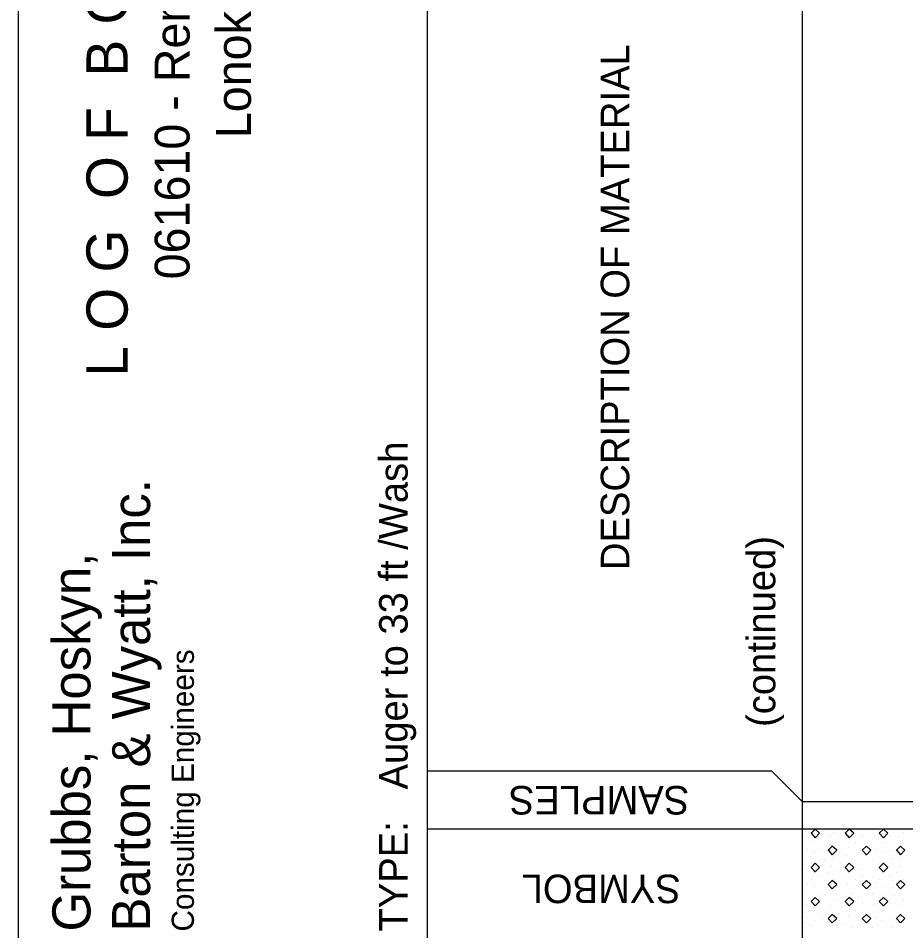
# Model space of a CAD drawing. Extents: x 1313964 to 1316843, y 2087046 to 2096619.
# Drawn here: x 1314075.31 to 1314091.13, y 2089930.61 to 2089946.89 of the extents above; entities that cross this region are included whole.
import ezdxf

# ---------------------------------------------------------------- set-up
doc = ezdxf.new("R2010")
doc.units = 0
doc.layers.add('B-Sub-Contour', color=7, linetype='Continuous')
doc.layers.add('Default', color=7, linetype='Continuous')

# ---------------------------------------------------------------- blocks, each defined once
blk = doc.blocks.new('POINT_DISPLAY')
at = {"layer": 'Default'}
blk.add_line((0, 0), (0, 0), dxfattribs=at)

msp = doc.modelspace()

# ---------------------------------------------------------------- linework, layer by layer
at = {"layer": 'B-Sub-Contour'}
for points in [[(1314136.725, 2089928.164), (1314136.725, 2089971.035), (1314075.306, 2089971.035), (1314075.306, 2089928.164), (1314136.725, 2089928.164)], [(1314082.603, 2089928.164), (1314082.603, 2089971.035)], [(1314089.292, 2089928.164), (1314089.292, 2089971.035)], [(1314088.745, 2089933.454), (1314082.603, 2089933.454)], [(1314089.292, 2089932.907), (1314088.745, 2089933.454)], [(1314134.292, 2089932.907), (1314089.292, 2089932.907)], [(1314134.292, 2089932.421), (1314082.603, 2089932.421)]]:
    msp.add_lwpolyline(points, dxfattribs=at)
for points in [[(1314089.517, 2089932.421), (1314089.444, 2089932.348), (1314089.517, 2089932.269), (1314089.597, 2089932.348)], [(1314090.126, 2089932.421), (1314090.053, 2089932.348), (1314090.126, 2089932.269), (1314090.205, 2089932.348)], [(1314090.734, 2089932.421), (1314090.661, 2089932.348), (1314090.734, 2089932.269), (1314090.813, 2089932.348)], [(1314089.822, 2089932.117), (1314089.749, 2089932.044), (1314089.822, 2089931.965), (1314089.901, 2089932.044)], [(1314090.43, 2089932.117), (1314090.357, 2089932.044), (1314090.43, 2089931.965), (1314090.509, 2089932.044)], [(1314091.038, 2089932.117), (1314090.965, 2089932.044), (1314091.038, 2089931.965), (1314091.117, 2089932.044)], [(1314089.517, 2089931.813), (1314089.444, 2089931.74), (1314089.517, 2089931.661), (1314089.597, 2089931.74)], [(1314090.126, 2089931.813), (1314090.053, 2089931.74), (1314090.126, 2089931.661), (1314090.205, 2089931.74)], [(1314090.734, 2089931.813), (1314090.661, 2089931.74), (1314090.734, 2089931.661), (1314090.813, 2089931.74)], [(1314089.822, 2089931.508), (1314089.749, 2089931.436), (1314089.822, 2089931.356), (1314089.901, 2089931.436)], [(1314090.43, 2089931.508), (1314090.357, 2089931.436), (1314090.43, 2089931.356), (1314090.509, 2089931.436)], [(1314091.038, 2089931.508), (1314090.965, 2089931.436), (1314091.038, 2089931.356), (1314091.117, 2089931.436)], [(1314089.517, 2089931.204), (1314089.444, 2089931.131), (1314089.517, 2089931.052), (1314089.597, 2089931.131)], [(1314090.126, 2089931.204), (1314090.053, 2089931.131), (1314090.126, 2089931.052), (1314090.205, 2089931.131)], [(1314090.734, 2089931.204), (1314090.661, 2089931.131), (1314090.734, 2089931.052), (1314090.813, 2089931.131)], [(1314089.822, 2089930.9), (1314089.749, 2089930.827), (1314089.822, 2089930.748), (1314089.901, 2089930.827)], [(1314090.43, 2089930.9), (1314090.357, 2089930.827), (1314090.43, 2089930.748), (1314090.509, 2089930.827)], [(1314091.038, 2089930.9), (1314090.965, 2089930.827), (1314091.038, 2089930.748), (1314091.117, 2089930.827)]]:
    msp.add_lwpolyline(points, close=True, dxfattribs=at)

# ---------------------------------------------------------------- block references
at = {"layer": 'B-Sub-Contour', "xscale": 0.019951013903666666, "yscale": 0.019951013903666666, "rotation": 90}
for p in [(1314089.353, 2089932.285), (1314089.444, 2089932.37), (1314089.627, 2089932.31), (1314089.782, 2089932.282), (1314089.87, 2089932.37), (1314089.992, 2089932.249), (1314090.113, 2089932.31), (1314090.357, 2089932.31), (1314090.569, 2089932.285), (1314090.661, 2089932.37), (1314090.843, 2089932.31), (1314090.998, 2089932.282), (1314091.086, 2089932.37), (1314089.384, 2089932.066), (1314089.505, 2089932.188), (1314089.749, 2089932.066), (1314089.931, 2089932.127), (1314090.113, 2089932.089), (1314090.235, 2089932.188), (1314090.478, 2089932.127), (1314090.6, 2089932.066), (1314090.722, 2089932.188), (1314090.965, 2089932.066), (1314089.439, 2089931.926), (1314089.505, 2089932.006), (1314089.643, 2089932.036), (1314089.829, 2089931.918), (1314089.956, 2089932.011), (1314090.053, 2089931.945), (1314090.296, 2089932.006), (1314090.417, 2089931.945), (1314090.655, 2089931.926), (1314090.722, 2089932.006), (1314090.86, 2089932.036), (1314091.045, 2089931.918), (1314089.323, 2089931.884), (1314089.566, 2089931.762), (1314089.688, 2089931.884), (1314089.809, 2089931.762), (1314089.992, 2089931.823), (1314090.174, 2089931.884), (1314090.539, 2089931.884), (1314090.782, 2089931.762), (1314090.904, 2089931.884), (1314091.026, 2089931.762), (1314089.323, 2089931.58), (1314089.384, 2089931.702), (1314089.505, 2089931.641), (1314089.627, 2089931.58), (1314089.749, 2089931.641), (1314089.931, 2089931.702), (1314090.113, 2089931.641), (1314090.296, 2089931.702), (1314090.357, 2089931.58), (1314090.539, 2089931.58), (1314090.6, 2089931.702), (1314090.722, 2089931.641), (1314090.843, 2089931.58), (1314090.965, 2089931.641), (1314089.384, 2089931.458), (1314089.444, 2089931.519), (1314089.688, 2089931.498), (1314089.809, 2089931.458), (1314089.87, 2089931.519), (1314090.1, 2089931.441), (1314090.235, 2089931.519), (1314090.417, 2089931.505), (1314090.6, 2089931.458), (1314090.661, 2089931.519), (1314090.904, 2089931.498), (1314091.026, 2089931.458), (1314091.086, 2089931.519), (1314089.323, 2089931.276), (1314089.505, 2089931.398), (1314089.566, 2089931.276), (1314089.704, 2089931.378), (1314089.809, 2089931.276), (1314089.931, 2089931.398), (1314090.174, 2089931.276), (1314090.296, 2089931.398), (1314090.478, 2089931.337), (1314090.539, 2089931.276), (1314090.722, 2089931.398), (1314090.782, 2089931.276), (1314090.921, 2089931.378), (1314091.026, 2089931.276), (1314089.444, 2089931.154), (1314089.627, 2089931.093), (1314089.696, 2089931.231), (1314089.87, 2089931.154), (1314090.053, 2089931.215), (1314090.113, 2089931.093), (1314090.296, 2089931.218), (1314090.357, 2089931.093), (1314090.661, 2089931.154), (1314090.843, 2089931.093), (1314090.912, 2089931.231), (1314091.086, 2089931.154), (1314089.353, 2089931.069), (1314089.505, 2089930.972), (1314089.782, 2089931.066), (1314089.992, 2089931.033), (1314090.235, 2089930.972), (1314090.569, 2089931.069), (1314090.722, 2089930.972), (1314090.998, 2089931.066), (1314089.384, 2089930.85), (1314089.505, 2089930.789), (1314089.643, 2089930.82), (1314089.749, 2089930.85), (1314089.931, 2089930.911), (1314089.956, 2089930.795), (1314090.113, 2089930.873), (1314090.296, 2089930.789), (1314090.478, 2089930.911), (1314090.6, 2089930.85), (1314090.722, 2089930.789), (1314090.86, 2089930.82), (1314090.965, 2089930.85), (1314089.323, 2089930.668), (1314089.439, 2089930.71), (1314089.688, 2089930.668), (1314089.829, 2089930.701), (1314090.053, 2089930.729), (1314090.174, 2089930.668), (1314090.417, 2089930.729), (1314090.539, 2089930.668), (1314090.655, 2089930.71), (1314090.904, 2089930.668), (1314091.045, 2089930.701)]:
    msp.add_blockref('POINT_DISPLAY', p, dxfattribs=at)

# ---------------------------------------------------------------- texts
at = {"layer": 'B-Sub-Contour'}
for s, height, rotation, p in [('L O G  O F  B O R I N G  N O.  S2', 0.7352, 90, (1314077.257, 2089940.493)), ('061610 - Remington Road over I-40', 0.62209, 90, (1314078.361, 2089942.229)), ('Lonoke County, Arkansas', 0.62209, 90, (1314079.455, 2089944.747)), ('DESCRIPTION OF MATERIAL', 0.50899, 90, (1314086.202, 2089937.043)), ('TYPE:   Auger to 33 ft /Wash', 0.50899, 90, (1314082.25, 2089930.596)), ('Barton & Wyatt, Inc.', 0.67865, 90, (1314077.657, 2089930.596)), ('(continued)', 0.50899, 90, (1314088.806, 2089934.245)), ('Grubbs, Hoskyn,', 0.67865, 90, (1314076.593, 2089930.596)), ('Consulting Engineers', 0.39588, 90, (1314078.438, 2089930.596)), ('SAMPLES', 0.509, 180, (1314087.271, 2089933.192)), ('SYMBOL', 0.509, 180, (1314087.12, 2089931.611))]:
    msp.add_text(s, height=height, rotation=rotation, dxfattribs=at).set_placement(p)

doc.saveas('drawing.dxf')
